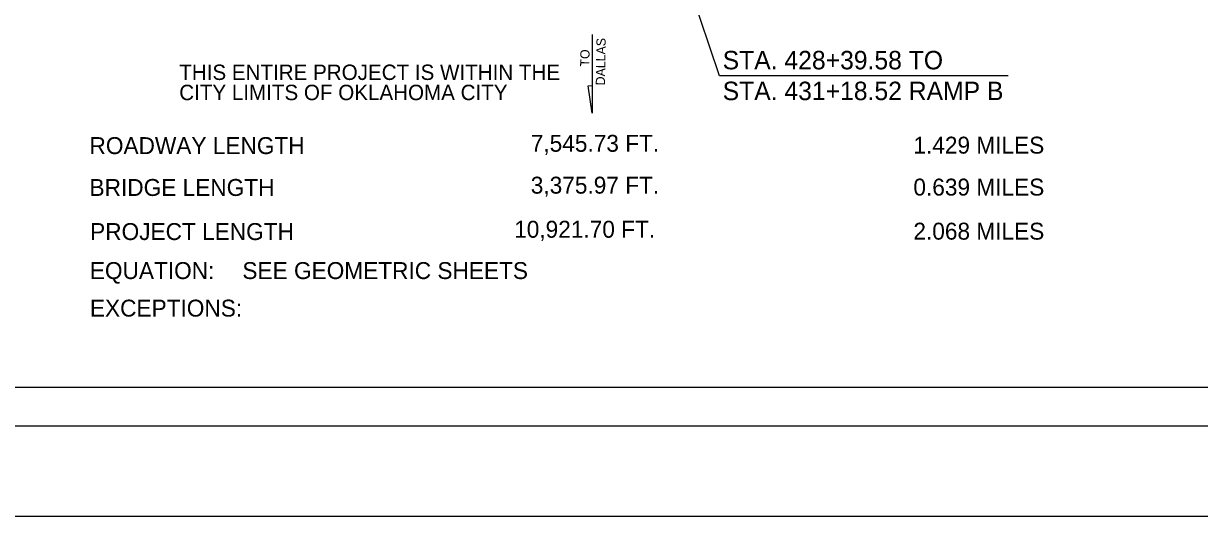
# Model space of a CAD drawing. Extents: x 2121385 to 2181200, y 132498 to 161273.
# Drawn here: x 2143424 to 2158702, y 132498 to 138905 of the extents above; entities that cross this region are included whole.
import ezdxf

# ---------------------------------------------------------------- set-up
doc = ezdxf.new("R2010")
doc.units = 0
for name, color, linetype in [('4', 7, 'Continuous'), ('5', 7, 'Continuous'), ('SHT_Plot_Shape_Full', 7, 'Continuous'), ('SHT_Plot_Shape_Half', 7, 'Continuous'), ('SHT_Sheet_Border', 7, 'Continuous'), ('SHT_Standard_Sheet_Txt', 7, 'Continuous')]:
    doc.layers.add(name, color=color, linetype=linetype)

msp = doc.modelspace()

# ---------------------------------------------------------------- linework, layer by layer
at = {"layer": '5'}
msp.add_line((2150813, 138762), (2150813, 138099), dxfattribs=at)
msp.add_lwpolyline([(2156215, 138224), (2152466, 138224), (2151084, 142325)], dxfattribs=at)
msp.add_lwpolyline([(2150812, 137741), (2150759, 138097), (2150813, 138099)], close=True, dxfattribs=at)
at = {"layer": 'SHT_Plot_Shape_Full'}
msp.add_lwpolyline([(2131361, 156498), (2167361, 156498), (2167361, 132498), (2131361, 132498)], close=True, dxfattribs=at)
at = {"layer": 'SHT_Plot_Shape_Half'}
msp.add_lwpolyline([(2132999, 155673), (2166999, 155673), (2166999, 133673), (2132999, 133673)], close=True, dxfattribs=at)
at = {"layer": 'SHT_Sheet_Border'}
msp.add_lwpolyline([(2166449, 134173), (2134949, 134173), (2134949, 155173), (2166449, 155173)], close=True, dxfattribs=at)

# ---------------------------------------------------------------- texts
at = {"layer": '4'}
for s, height, p in [('STA. 428+39.58 TO', 240, (2152507, 138309)), ('THIS ENTIRE PROJECT IS WITHIN THE', 200, (2145447, 138171)), ('STA. 431+18.52 RAMP B', 240, (2152507, 137909)), ('CITY LIMITS OF OKLAHOMA CITY', 200, (2145447, 137909))]:
    msp.add_text(s, height=height, dxfattribs=at).set_placement(p)
at = {"layer": 'SHT_Standard_Sheet_Txt'}
for s, p in [('DALLAS', (2150978, 138100)), ('TO', (2150775, 138345))]:
    msp.add_text(s, height=120, rotation=89.0899, dxfattribs=at).set_placement(p)
for s, p in [('ROADWAY LENGTH', (2144281, 137208)), ('7,545.73 FT.', (2150014, 137238)), ('1.429 MILES', (2154985, 137214)), ('3,375.97 FT.', (2150014, 136694)), ('BRIDGE LENGTH', (2144281, 136664)), ('0.639 MILES', (2154985, 136669)), ('PROJECT LENGTH', (2144289, 136091)), ('10,921.70 FT.', (2149798, 136121)), ('2.068 MILES', (2154985, 136096)), ('EQUATION:', (2144285, 135584)), ('SEE GEOMETRIC SHEETS', (2146267, 135584)), ('EXCEPTIONS:', (2144286, 135096))]:
    msp.add_text(s, height=220, dxfattribs=at).set_placement(p)

doc.saveas('drawing.dxf')
